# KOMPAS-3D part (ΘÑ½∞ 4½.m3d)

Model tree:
1. Эскиз:1
2. Операция выдавливания:1
     Расстояние 1 = 2
3. Эскиз:2
4. Операция выдавливания:2
     Расстояние 1 = 5
5. Эскиз:3
6. Операция выдавливания:3
     Расстояние 1 = 2
7. Эскиз:4
8. Операция выдавливания:4
     Расстояние 1 = 78
9. Эскиз:5
10. Операция выдавливания:5
     Расстояние 1 = 2
11. Эскиз:6
12. Операция выдавливания:6
     Расстояние 1 = 4.5
13. Эскиз:7
14. Операция выдавливания:7
     Расстояние 1 = 2
15. Скругление:1
     Радиус = 1
16. Скругление:2
     Радиус = 1
17. Эскиз:8
18. Вырезать элемент выдавливания:1
     Расстояние 1 = 10; Угол 1 = 35
19. Эскиз:9
20. Вырезать элемент выдавливания:2
     Расстояние 1 = 10; Угол 1 = 35
21. Эскиз:10
22. Вырезать элемент выдавливания:3
     Расстояние 2 = 22; Расстояние 1 = 22; Угол 1 = 35
23. Эскиз:11
24. Вырезать элемент выдавливания:4
     Расстояние 2 = 2; Расстояние 1 = 2
25. Эскиз:12
26. Вырезать элемент выдавливания:5
     Расстояние 2 = 2; Расстояние 1 = 2; Угол 1 = 35
27. Эскиз:13
28. Вырезать элемент выдавливания:6
     Расстояние 2 = 2; Расстояние 1 = 122
29. Эскиз:14
30. Вырезать элемент выдавливания:7
     Расстояние 2 = 100; Расстояние 1 = 60
